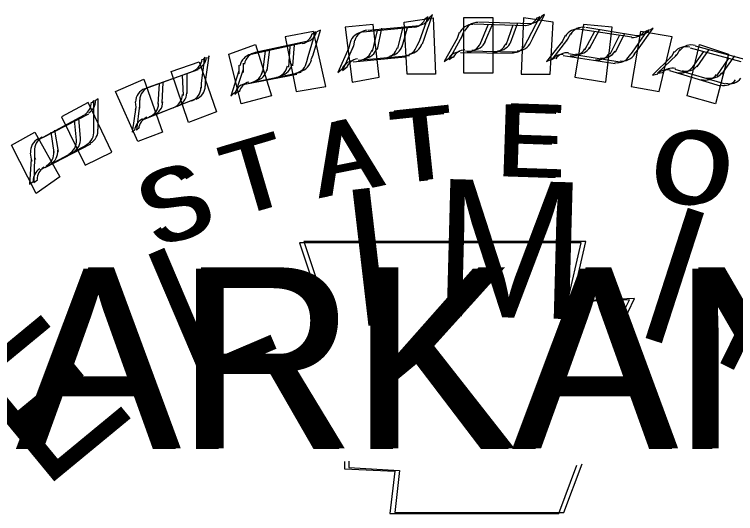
# Model space of a CAD drawing. Extents: x -1063117.9 to -1063075.9, y -253323.6 to -253301.6.
# Drawn here: x -1063092.649 to -1063091.9, y -253320.647 to -253320.129 of the extents above; entities that cross this region are included whole.
import ezdxf

# ---------------------------------------------------------------- set-up
doc = ezdxf.new("R2010")
doc.units = 0
for name, color, linetype in [('Border 2660-Hwy18 - STAMP PRELIM', 7, 'Continuous'), ('Border 2660-Hwy18 - Stamp-ChrisC', 7, 'Continuous'), ('Stamp Charles W', 7, 'Continuous')]:
    doc.layers.add(name, color=color, linetype=linetype)

msp = doc.modelspace()

# ---------------------------------------------------------------- linework, layer by layer
at = {"layer": 'Border 2660-Hwy18 - STAMP PRELIM'}
for p, q in [((-1063092.24413, -253320.13716), (-1063092.21413, -253320.13266)), ((-1063092.21413, -253320.13266), (-1063092.21183, -253320.19116)), ((-1063092.15183, -253320.13266), (-1063092.18263, -253320.13266)), ((-1063092.18263, -253320.13266), (-1063092.18263, -253320.18966)), ((-1063092.15183, -253320.18966), (-1063092.15183, -253320.13266)), ((-1063092.12033, -253320.13266), (-1063092.12263, -253320.19116)), ((-1063092.08963, -253320.13716), (-1063092.12033, -253320.13266)), ((-1063092.27633, -253320.13936), (-1063092.30563, -253320.14236)), ((-1063092.30563, -253320.14236), (-1063092.29813, -253320.19936)), ((-1063092.27033, -253320.19416), (-1063092.27633, -253320.13936)), ((-1063092.24113, -253320.19116), (-1063092.24413, -253320.13716)), ((-1063092.09263, -253320.19116), (-1063092.08963, -253320.13716)), ((-1063092.05813, -253320.13936), (-1063092.06713, -253320.19416)), ((-1063092.02813, -253320.14236), (-1063092.05813, -253320.13936)), ((-1063092.03483, -253320.19936), (-1063092.02813, -253320.14236)), ((-1063092.33863, -253320.14686), (-1063092.36783, -253320.15216)), ((-1063092.32583, -253320.20386), (-1063092.33863, -253320.14686)), ((-1063091.99883, -253320.14686), (-1063092.00863, -253320.20386)), ((-1063091.96583, -253320.15216), (-1063091.99883, -253320.14686)), ((-1063092.36783, -253320.15216), (-1063092.35663, -253320.20916)), ((-1063091.97933, -253320.20916), (-1063091.96583, -253320.15216)), ((-1063092.42633, -253320.17016), (-1063092.39863, -253320.16036)), ((-1063092.39863, -253320.16036), (-1063092.38213, -253320.21366)), ((-1063091.95013, -253320.21366), (-1063091.93733, -253320.16036)), ((-1063091.93733, -253320.16036), (-1063091.90733, -253320.17016)), ((-1063092.41363, -253320.22186), (-1063092.42633, -253320.17016)), ((-1063091.90733, -253320.17016), (-1063091.92083, -253320.22186)), ((-1063092.48633, -253320.18816), (-1063092.45713, -253320.17836)), ((-1063092.45713, -253320.17836), (-1063092.43913, -253320.23016)), ((-1063092.46833, -253320.24136), (-1063092.48633, -253320.18816)), ((-1063092.29813, -253320.19936), (-1063092.27033, -253320.19416)), ((-1063092.21183, -253320.19116), (-1063092.24113, -253320.19116)), ((-1063092.18263, -253320.18966), (-1063092.15183, -253320.18966)), ((-1063092.12263, -253320.19116), (-1063092.09263, -253320.19116)), ((-1063092.06713, -253320.19416), (-1063092.03483, -253320.19936)), ((-1063092.54413, -253320.20916), (-1063092.51483, -253320.19636)), ((-1063092.51483, -253320.19636), (-1063092.49533, -253320.25116)), ((-1063092.52083, -253320.26086), (-1063092.54413, -253320.20916)), ((-1063092.35663, -253320.20916), (-1063092.32583, -253320.20386)), ((-1063092.00863, -253320.20386), (-1063091.97933, -253320.20916)), ((-1063092.38213, -253320.21366), (-1063092.41363, -253320.22186)), ((-1063091.92083, -253320.22186), (-1063091.95013, -253320.21366)), ((-1063092.57263, -253320.22036), (-1063092.60033, -253320.23536)), ((-1063092.54783, -253320.27216), (-1063092.57263, -253320.22036)), ((-1063092.43913, -253320.23016), (-1063092.46833, -253320.24136)), ((-1063092.60033, -253320.23536), (-1063092.57563, -253320.28566)), ((-1063092.65213, -253320.26466), (-1063092.62813, -253320.25116)), ((-1063092.62813, -253320.25116), (-1063092.60183, -253320.29766)), ((-1063092.49533, -253320.25116), (-1063092.52083, -253320.26086)), ((-1063092.62663, -253320.31486), (-1063092.65213, -253320.26466)), ((-1063092.57563, -253320.28566), (-1063092.54783, -253320.27216)), ((-1063092.60183, -253320.29766), (-1063092.62663, -253320.31486))]:
    msp.add_line(p, q, dxfattribs=at)
at = {"layer": 'Border 2660-Hwy18 - Stamp-ChrisC'}
for p, q in [((-1063092.22839, -253320.1569), (-1063092.21939, -253320.1314)), ((-1063092.21939, -253320.1314), (-1063092.22239, -253320.1337)), ((-1063092.11589, -253320.1554), (-1063092.10319, -253320.1314)), ((-1063092.10319, -253320.1314), (-1063092.10619, -253320.1329)), ((-1063092.28689, -253320.1472), (-1063092.23289, -253320.1419)), ((-1063092.17219, -253320.1389), (-1063092.11819, -253320.1404)), ((-1063092.16539, -253320.1599), (-1063092.15719, -253320.1397)), ((-1063092.13839, -253320.1607), (-1063092.13089, -253320.1397)), ((-1063092.34389, -253320.1727), (-1063092.33639, -253320.1472)), ((-1063092.33639, -253320.1472), (-1063092.33939, -253320.1494)), ((-1063092.27719, -253320.1674), (-1063092.27189, -253320.1457)), ((-1063092.25089, -253320.1644), (-1063092.24569, -253320.1434)), ((-1063092.18719, -253320.1479), (-1063092.18939, -253320.1539)), ((-1063092.06119, -253320.1442), (-1063092.00789, -253320.1524)), ((-1063092.05669, -253320.1659), (-1063092.04619, -253320.1464)), ((-1063092.00719, -253320.1682), (-1063091.99139, -253320.1457)), ((-1063091.99139, -253320.1457), (-1063091.99439, -253320.1472)), ((-1063092.30039, -253320.1577), (-1063092.30189, -253320.1637)), ((-1063092.23069, -253320.1614), (-1063092.22839, -253320.1569)), ((-1063092.18939, -253320.1539), (-1063092.20289, -253320.1779)), ((-1063092.18939, -253320.1539), (-1063092.19019, -253320.1562)), ((-1063092.11819, -253320.1599), (-1063092.11589, -253320.1554)), ((-1063092.07989, -253320.1569), (-1063092.09639, -253320.1779)), ((-1063092.07989, -253320.1569), (-1063092.08069, -253320.1584)), ((-1063092.07689, -253320.1509), (-1063092.07989, -253320.1569)), ((-1063092.03039, -253320.1704), (-1063092.02069, -253320.1509)), ((-1063092.40319, -253320.1704), (-1063092.34989, -253320.1584)), ((-1063092.36419, -253320.1839), (-1063092.36269, -253320.1622)), ((-1063092.30189, -253320.1637), (-1063092.31319, -253320.1892)), ((-1063092.30189, -253320.1637), (-1063092.30269, -253320.1659)), ((-1063091.94719, -253320.1637), (-1063091.89469, -253320.1779)), ((-1063092.39119, -253320.1892), (-1063092.38819, -253320.1667)), ((-1063092.13089, -253320.1697), (-1063092.18569, -253320.1689)), ((-1063092.02519, -253320.1802), (-1063092.07919, -253320.1719)), ((-1063092.01019, -253320.1719), (-1063092.00719, -253320.1682)), ((-1063091.96369, -253320.1674), (-1063091.96669, -253320.1727)), ((-1063091.94569, -253320.1854), (-1063091.93289, -253320.1674)), ((-1063092.45489, -253320.2004), (-1063092.45119, -253320.1734)), ((-1063092.45119, -253320.1734), (-1063092.45339, -253320.1764)), ((-1063092.34539, -253320.1779), (-1063092.34389, -253320.1727)), ((-1063092.24339, -253320.1734), (-1063092.29739, -253320.1787)), ((-1063092.20289, -253320.1779), (-1063092.19839, -253320.1749)), ((-1063092.09639, -253320.1779), (-1063092.09189, -253320.1757)), ((-1063091.96669, -253320.1727), (-1063091.98619, -253320.1922)), ((-1063091.96669, -253320.1727), (-1063091.96819, -253320.1742)), ((-1063091.91939, -253320.1929), (-1063091.90669, -253320.1742)), ((-1063092.41589, -253320.1817), (-1063092.41589, -253320.1877)), ((-1063092.31319, -253320.1892), (-1063092.30869, -253320.1854)), ((-1063092.51419, -253320.2064), (-1063092.46239, -253320.1877)), ((-1063092.47369, -253320.2132), (-1063092.47439, -253320.1922)), ((-1063092.41589, -253320.1877), (-1063092.42419, -253320.2139)), ((-1063092.41589, -253320.1877), (-1063092.41589, -253320.1907)), ((-1063092.35589, -253320.1914), (-1063092.40989, -253320.2019)), ((-1063091.98619, -253320.1922), (-1063091.98089, -253320.1907)), ((-1063091.91569, -253320.2034), (-1063091.96819, -253320.1877)), ((-1063092.49989, -253320.2222), (-1063092.49839, -253320.2012)), ((-1063092.45489, -253320.2057), (-1063092.45489, -253320.2004)), ((-1063092.42419, -253320.2139), (-1063092.42039, -253320.2102)), ((-1063092.56669, -253320.2184), (-1063092.56889, -253320.2207)), ((-1063092.56669, -253320.2447), (-1063092.56669, -253320.2184)), ((-1063092.52389, -253320.2199), (-1063092.52319, -253320.2252)), ((-1063092.46469, -253320.2184), (-1063092.51639, -253320.2387)), ((-1063092.52319, -253320.2252), (-1063092.52689, -253320.2514)), ((-1063092.52319, -253320.2252), (-1063092.52389, -253320.2282)), ((-1063092.62369, -253320.2589), (-1063092.57639, -253320.2334)), ((-1063092.58469, -253320.2597), (-1063092.58689, -253320.2387)), ((-1063092.56669, -253320.2499), (-1063092.56669, -253320.2447)), ((-1063092.60789, -253320.2724), (-1063092.61089, -253320.2514)), ((-1063092.52689, -253320.2514), (-1063092.52389, -253320.2484)), ((-1063092.57419, -253320.2649), (-1063092.62219, -253320.2904)), ((-1063092.63269, -253320.2732), (-1063092.63189, -253320.2792)), ((-1063092.63189, -253320.2792), (-1063092.63339, -253320.3054)), ((-1063092.63189, -253320.2792), (-1063092.63119, -253320.2814)), ((-1063092.63339, -253320.3054), (-1063092.62969, -253320.3024))]:
    msp.add_line(p, q, dxfattribs=at)
for points in [[(-1063092.35289, -253320.3662), (-1063092.32739, -253320.4434)], [(-1063092.02369, -253320.4524), (-1063092.01019, -253320.4254), (-1063092.07469, -253320.4277), (-1063092.06039, -253320.3662), (-1063092.35289, -253320.3662)], [(-1063092.30639, -253320.5934), (-1063092.30639, -253320.6009), (-1063092.25389, -253320.6032), (-1063092.25919, -253320.6474), (-1063092.08369, -253320.6474), (-1063092.06489, -253320.5972)]]:
    msp.add_lwpolyline(points, dxfattribs=at)
for centre, start, end in [((-1063092.23599, -253320.12769), 279.92492, 338.71276), ((-1063092.11935, -253320.12566), 273.42361, 332.21146), ((-1063092.17304, -253320.15417), 89.16284, 157.53681), ((-1063092.35425, -253320.14514), 286.27006, 345.0579), ((-1063092.2861, -253320.16211), 95.66414, 164.03812), ((-1063092.064, -253320.15908), 81.42307, 149.79704), ((-1063092.00697, -253320.13805), 265.68385, 324.47169), ((-1063092.26554, -253320.15931), 275.66414, 344.03812), ((-1063092.24512, -253320.15722), 275.66414, 344.03812), ((-1063092.17873, -253320.15323), 269.16284, 337.53681), ((-1063092.1523, -253320.15372), 269.16284, 337.53681), ((-1063092.13177, -253320.15396), 269.16284, 337.53681), ((-1063092.06952, -253320.15738), 261.42307, 329.79704), ((-1063091.95172, -253320.17739), 73.99093, 142.3649), ((-1063092.40025, -253320.18488), 102.00928, 170.38325), ((-1063092.29186, -253320.16182), 275.66414, 344.03812), ((-1063092.18545, -253320.18248), 93.42361, 152.21146), ((-1063092.08012, -253320.18546), 85.68385, 144.47169), ((-1063092.04339, -253320.16143), 261.42307, 329.79704), ((-1063092.02308, -253320.16443), 261.42307, 329.79704), ((-1063092.46894, -253320.17392), 294.83706, 353.62491), ((-1063092.36006, -253320.1755), 282.00928, 350.38325), ((-1063092.29522, -253320.19164), 99.92492, 158.71276), ((-1063092.38013, -253320.17983), 282.00928, 350.38325), ((-1063091.97111, -253320.20146), 78.25171, 137.03955), ((-1063091.95697, -253320.175), 253.99093, 322.3649), ((-1063092.40601, -253320.18523), 282.00928, 350.38325), ((-1063091.93159, -253320.18238), 253.99093, 322.3649), ((-1063092.40606, -253320.21524), 106.27006, 165.0579), ((-1063091.91183, -253320.18799), 253.99093, 322.3649), ((-1063092.50851, -253320.22007), 110.57629, 178.95026), ((-1063092.47016, -253320.2048), 290.57629, 358.95026), ((-1063092.48936, -253320.21208), 290.57629, 358.95026), ((-1063092.58403, -253320.22049), 301.95449, 0.74233), ((-1063092.51415, -253320.22127), 290.57629, 358.95026), ((-1063092.50973, -253320.25095), 114.83706, 173.62491), ((-1063092.58142, -253320.25129), 297.69371, 6.06769), ((-1063092.61758, -253320.27119), 117.69371, 186.06769), ((-1063092.59957, -253320.26088), 297.69371, 6.06769), ((-1063092.62303, -253320.27308), 297.69371, 6.06769), ((-1063092.61496, -253320.30198), 121.95449, 180.74233)]:
    msp.add_arc(centre, 0.01481, start, end, dxfattribs=at)
at = {"layer": 'Stamp Charles W'}
for p, q in [((-1063092.22344, -253320.1548), (-1063092.21485, -253320.12902)), ((-1063092.21485, -253320.12902), (-1063092.21771, -253320.13189)), ((-1063092.11079, -253320.15384), (-1063092.09838, -253320.12902)), ((-1063092.09838, -253320.12902), (-1063092.10125, -253320.13093)), ((-1063092.28167, -253320.14525), (-1063092.22821, -253320.14048)), ((-1063092.24635, -253320.16243), (-1063092.24062, -253320.14143)), ((-1063092.16711, -253320.13666), (-1063092.1127, -253320.13857)), ((-1063092.16043, -253320.15766), (-1063092.15184, -253320.13761)), ((-1063092.1337, -253320.15862), (-1063092.12607, -253320.13761)), ((-1063092.05542, -253320.14239), (-1063092.00292, -253320.15098)), ((-1063092.33895, -253320.17103), (-1063092.33131, -253320.14525)), ((-1063092.33131, -253320.14525), (-1063092.33513, -253320.14716)), ((-1063092.27212, -253320.1653), (-1063092.26735, -253320.14334)), ((-1063092.18239, -253320.14621), (-1063092.1843, -253320.15193)), ((-1063092.07165, -253320.14907), (-1063092.07452, -253320.1548)), ((-1063092.0516, -253320.16434), (-1063092.0411, -253320.1443)), ((-1063092.02488, -253320.16816), (-1063092.01533, -253320.14907)), ((-1063092.00196, -253320.16625), (-1063091.98574, -253320.14334)), ((-1063091.98574, -253320.14334), (-1063091.9886, -253320.14525)), ((-1063092.39909, -253320.16816), (-1063092.34563, -253320.15671)), ((-1063092.29599, -253320.15575), (-1063092.29694, -253320.16148)), ((-1063092.22535, -253320.15957), (-1063092.22344, -253320.1548)), ((-1063092.1843, -253320.15193), (-1063092.19766, -253320.1758)), ((-1063092.1843, -253320.15193), (-1063092.18525, -253320.15384)), ((-1063092.1127, -253320.15766), (-1063092.11079, -253320.15384)), ((-1063092.07452, -253320.1548), (-1063092.09074, -253320.1758)), ((-1063092.07452, -253320.1548), (-1063092.07547, -253320.15671)), ((-1063092.35995, -253320.18248), (-1063092.35804, -253320.16053)), ((-1063092.29694, -253320.16148), (-1063092.3084, -253320.18725)), ((-1063092.29694, -253320.16148), (-1063092.2979, -253320.16434)), ((-1063091.94182, -253320.16148), (-1063091.88932, -253320.1758)), ((-1063092.45064, -253320.19871), (-1063092.44682, -253320.17198)), ((-1063092.44682, -253320.17198), (-1063092.44873, -253320.17484)), ((-1063092.38668, -253320.18725), (-1063092.38381, -253320.1653)), ((-1063092.34086, -253320.1758), (-1063092.33895, -253320.17103)), ((-1063092.23871, -253320.17198), (-1063092.29217, -253320.17675)), ((-1063092.12607, -253320.16816), (-1063092.18048, -253320.16721)), ((-1063092.0201, -253320.17866), (-1063092.07356, -253320.17007)), ((-1063092.00483, -253320.17007), (-1063092.00196, -253320.16625)), ((-1063091.96092, -253320.17103), (-1063091.98096, -253320.19012)), ((-1063091.96092, -253320.17103), (-1063091.96282, -253320.17198)), ((-1063091.95805, -253320.1653), (-1063091.96092, -253320.17103)), ((-1063091.93991, -253320.18344), (-1063091.9275, -253320.1653)), ((-1063091.91414, -253320.19107), (-1063091.90077, -253320.17198)), ((-1063092.4115, -253320.17962), (-1063092.4115, -253320.1863)), ((-1063092.19766, -253320.1758), (-1063092.19384, -253320.17294)), ((-1063092.09074, -253320.1758), (-1063092.08693, -253320.17389)), ((-1063092.50983, -253320.20444), (-1063092.45828, -253320.1863)), ((-1063092.4115, -253320.1863), (-1063092.42009, -253320.21207)), ((-1063092.4115, -253320.1863), (-1063092.4115, -253320.18916)), ((-1063092.3084, -253320.18725), (-1063092.30363, -253320.18344)), ((-1063091.91032, -253320.20157), (-1063091.96282, -253320.1863)), ((-1063092.46973, -253320.21112), (-1063092.46973, -253320.19012)), ((-1063092.35136, -253320.18916), (-1063092.40577, -253320.20062)), ((-1063091.98096, -253320.19012), (-1063091.97523, -253320.18916)), ((-1063092.49551, -253320.22067), (-1063092.49455, -253320.19966)), ((-1063092.45064, -253320.20348), (-1063092.45064, -253320.19871)), ((-1063092.42009, -253320.21207), (-1063092.41627, -253320.20826)), ((-1063092.56233, -253320.21685), (-1063092.56519, -253320.21876)), ((-1063092.56233, -253320.24262), (-1063092.56233, -253320.21685)), ((-1063092.46019, -253320.21685), (-1063092.51173, -253320.2369)), ((-1063092.51937, -253320.22353), (-1063092.52224, -253320.24931)), ((-1063092.51937, -253320.2178), (-1063092.51937, -253320.22353)), ((-1063092.51937, -253320.22353), (-1063092.51937, -253320.22639)), ((-1063092.61961, -253320.25694), (-1063092.57188, -253320.23212)), ((-1063092.58047, -253320.2579), (-1063092.58238, -253320.2369)), ((-1063092.56233, -253320.24835), (-1063092.56233, -253320.24262)), ((-1063092.52224, -253320.24931), (-1063092.51937, -253320.24644)), ((-1063092.60338, -253320.27126), (-1063092.6072, -253320.24931)), ((-1063092.56997, -253320.26362), (-1063092.6177, -253320.28845)), ((-1063092.6282, -253320.27126), (-1063092.6282, -253320.27794)), ((-1063092.6282, -253320.27794), (-1063092.62915, -253320.30372)), ((-1063092.6282, -253320.27794), (-1063092.62724, -253320.27985)), ((-1063092.62915, -253320.30372), (-1063092.62534, -253320.30086))]:
    msp.add_line(p, q, dxfattribs=at)
for points in [[(-1063092.34849, -253320.36482), (-1063092.32272, -253320.44214)], [(-1063092.01819, -253320.45169), (-1063092.00483, -253320.424), (-1063092.06974, -253320.42687), (-1063092.05542, -253320.36482), (-1063092.34849, -253320.36482)], [(-1063092.30172, -253320.59297), (-1063092.30172, -253320.59965), (-1063092.24921, -253320.60252), (-1063092.25399, -253320.64643), (-1063092.07833, -253320.64643), (-1063092.05924, -253320.59583)]]:
    msp.add_lwpolyline(points, dxfattribs=at)
for centre, start, end in [((-1063092.23101, -253320.12574), 279.92492, 338.71276), ((-1063092.11411, -253320.12369), 273.42361, 332.21146), ((-1063092.16791, -253320.15227), 89.16284, 157.53681), ((-1063092.05864, -253320.15719), 81.42307, 149.79704), ((-1063092.34953, -253320.14322), 286.27006, 345.0579), ((-1063092.28123, -253320.16023), 95.66414, 164.03812), ((-1063092.00148, -253320.13612), 265.68385, 324.47169), ((-1063092.17362, -253320.15133), 269.16284, 337.53681), ((-1063092.14713, -253320.15182), 269.16284, 337.53681), ((-1063092.287, -253320.15994), 275.66414, 344.03812), ((-1063092.26062, -253320.15742), 275.66414, 344.03812), ((-1063092.24015, -253320.15533), 275.66414, 344.03812), ((-1063092.12655, -253320.15206), 269.16284, 337.53681), ((-1063092.06416, -253320.15549), 261.42307, 329.79704), ((-1063091.9461, -253320.17554), 73.99093, 142.3649), ((-1063092.39563, -253320.18305), 102.00928, 170.38325), ((-1063092.18035, -253320.18064), 93.42361, 152.21146), ((-1063092.07478, -253320.18363), 85.68385, 144.47169), ((-1063092.03798, -253320.15954), 261.42307, 329.79704), ((-1063092.01762, -253320.16255), 261.42307, 329.79704), ((-1063092.46448, -253320.17206), 294.83706, 353.62491), ((-1063092.35535, -253320.17364), 282.00928, 350.38325), ((-1063092.29037, -253320.18982), 99.92492, 158.71276), ((-1063092.4014, -253320.1834), 282.00928, 350.38325), ((-1063092.37547, -253320.17799), 282.00928, 350.38325), ((-1063091.96553, -253320.19967), 78.25171, 137.03955), ((-1063091.95136, -253320.17314), 253.99093, 322.3649), ((-1063091.92592, -253320.18055), 253.99093, 322.3649), ((-1063092.40145, -253320.21347), 106.27006, 165.0579), ((-1063091.90613, -253320.18616), 253.99093, 322.3649), ((-1063092.50413, -253320.21831), 110.57629, 178.95026), ((-1063092.4657, -253320.20301), 290.57629, 358.95026), ((-1063092.48495, -253320.2103), 290.57629, 358.95026), ((-1063092.57983, -253320.21874), 301.95449, 0.74233), ((-1063092.50979, -253320.21952), 290.57629, 358.95026), ((-1063092.50536, -253320.24927), 114.83706, 173.62491), ((-1063092.57721, -253320.2496), 297.69371, 6.06769), ((-1063092.61344, -253320.26955), 117.69371, 186.06769), ((-1063092.5954, -253320.25922), 297.69371, 6.06769), ((-1063092.61891, -253320.27145), 297.69371, 6.06769), ((-1063092.61082, -253320.30041), 121.95449, 180.74233)]:
    msp.add_arc(centre, 0.01484, start, end, dxfattribs=at)

# ---------------------------------------------------------------- texts
at = {"layer": 'Border 2660-Hwy18 - STAMP PRELIM'}
for s, rotation, p in [('M', 358.46666, (-1063092.21563, -253320.44165)), ('I', 6.67523, (-1063092.29883, -253320.45435)), ('I', 342.04953, (-1063092.01013, -253320.45965)), ('N', 333.84096, (-1063091.92983, -253320.48435)), ('L', 23.09236, (-1063092.46833, -253320.51515)), ('E', 39.5095, (-1063092.61983, -253320.62385))]:
    msp.add_text(s, height=0.14209, rotation=rotation, dxfattribs=at).set_placement(p)
at = {"layer": 'Border 2660-Hwy18 - Stamp-ChrisC'}
for s, height, rotation, p in [('T', 0.075, 6.02276, (-1063092.25439, -253320.3051)), ('E', 0.07499, 358.07323, (-1063092.14939, -253320.2969)), ('A', 0.075, 11.21318, (-1063092.33319, -253320.3201)), ('T', 0.07499, 16.4036, (-1063092.42019, -253320.3404)), ('O', 0.07498, 350.4515, (-1063091.99269, -253320.3194)), ('S', 0.07499, 21.59401, (-1063092.50269, -253320.3734))]:
    msp.add_text(s, height=height, rotation=rotation, dxfattribs=at).set_placement(p)
msp.add_text('ARKANSAS', height=0.187497, dxfattribs=at).set_placement((-1063092.64819, -253320.5804))
at = {"layer": 'Stamp Charles W'}
for s, height, rotation, p in [('T', 0.07517, 6.02276, (-1063092.24921, -253320.30372)), ('E', 0.07515, 358.07323, (-1063092.1442, -253320.29608)), ('A', 0.07517, 11.21318, (-1063092.32845, -253320.31899)), ('O', 0.07514, 350.4515, (-1063091.98669, -253320.31804)), ('T', 0.07515, 16.4036, (-1063092.41532, -253320.33904)), ('S', 0.07515, 21.59401, (-1063092.49742, -253320.37245))]:
    msp.add_text(s, height=height, rotation=rotation, dxfattribs=at).set_placement(p)
msp.add_text('ARKANSAS', height=0.187911, dxfattribs=at).set_placement((-1063092.64347, -253320.57961))

doc.saveas('drawing.dxf')
